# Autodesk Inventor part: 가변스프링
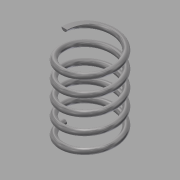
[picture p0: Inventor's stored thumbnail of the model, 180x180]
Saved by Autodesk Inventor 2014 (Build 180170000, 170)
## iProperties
Created: 2018-12
Part Number: 가변스프링
Material: 스테인레스 스틸
Document SubType Name: Modeling
Designer: kh
Density: 8.08 g/cm^3
Appearance: 반연마
Mass: 7.07161 g
Surface Area: 17.7586 cm^2
Volume: 0.875199 cm^3
Author: kh
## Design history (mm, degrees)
sketch "스케치1"
  geometry: L1 (0, 0)-(9, 0); L2 (9, 0)-(9, 28.5); L3 (9, 28.5)-(0, 28.5); L4 (0, 28.5)-(0, 0); C1 r 1 at (9, 0)
  constraints: 8 end point, 2 parallel, 1 centre point, 1 coincident, 1 horizontal, 1 perpendicular
  dimensions: "d0" = 28.5 distance of L1.end L2.end (derived); "d1" = 18 diameter of L2 L4; "d2" = 2 diameter of C1
feature "코일1" pitch "d3" = 10; turns "d5" = 5; dims "d4" = 28.5 (= d0), "d6" = 0, angle "d7" = 90 deg, angle "d8" = 90 deg, "d9" = 0, "d10" = 0
feature "분할1"
node "작업 평면1"
feature "분할2"
node "솔리드1"
